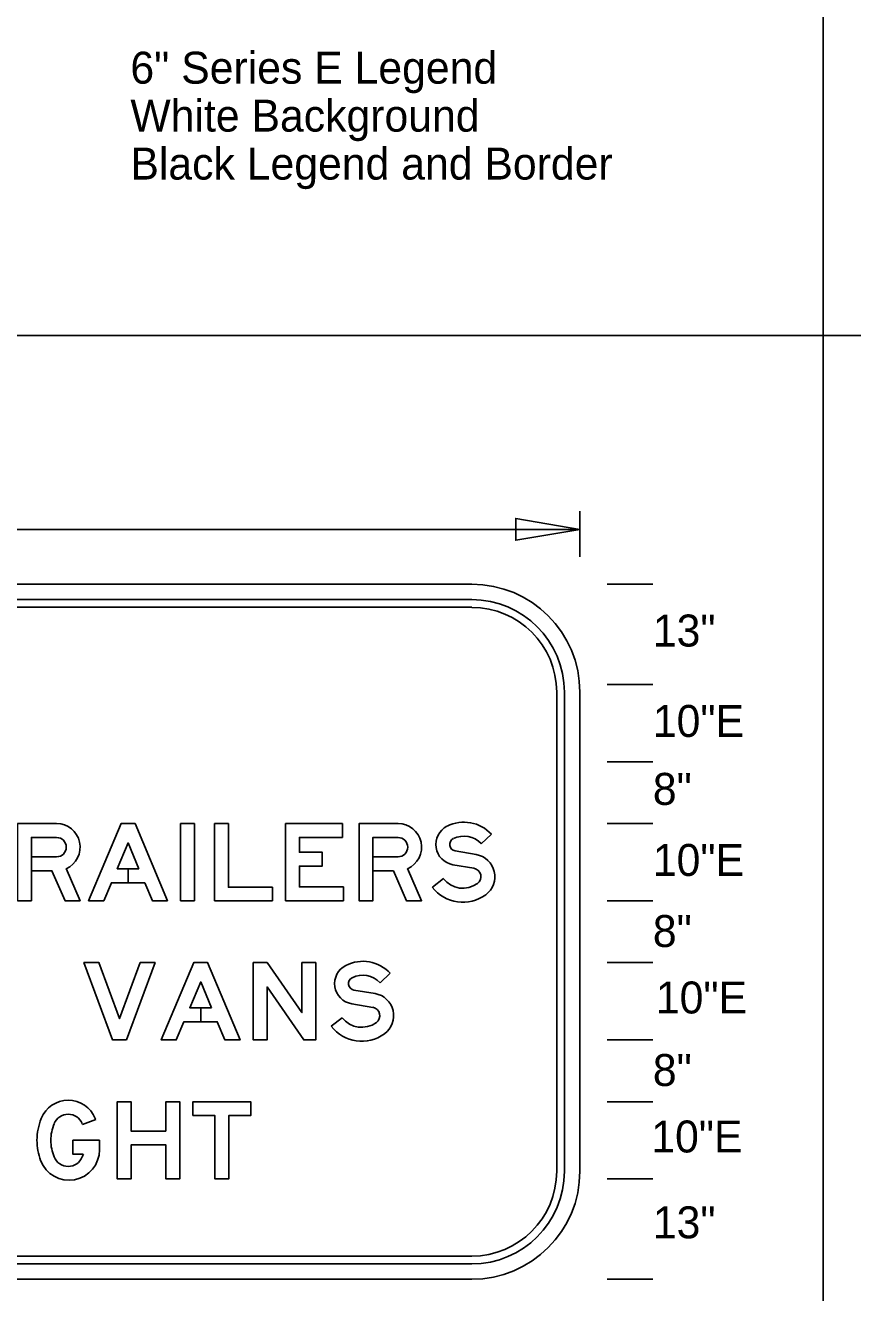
# Model space of a CAD drawing. Extents: x 0 to 770, y 0 to 495.
# Drawn here: x 297.9 to 388.5, y 225.2 to 363.9 of the extents above; entities that cross this region are included whole.
import ezdxf

# ---------------------------------------------------------------- set-up
doc = ezdxf.new("R2010")
doc.units = 0
for name, color, linetype in [('Dimension', 7, 'Continuous'), ('GSBWFill', 7, 'Continuous'), ('GSColorFill', 7, 'Continuous'), ('GSDims', 7, 'Continuous'), ('GSOutline', 7, 'Continuous'), ('SheetLines_dp', 7, 'Continuous'), ('TextStructures', 7, 'Continuous')]:
    doc.layers.add(name, color=color, linetype=linetype)

msp = doc.modelspace()

# ---------------------------------------------------------------- linework, layer by layer
at = {"layer": 'Dimension'}
msp.add_lwpolyline([(358.65, 308.76), (351.63, 309.95), (351.63, 307.57)], close=True, dxfattribs=at)
at = {"layer": 'GSBWFill'}
for p, q in [((346.81, 302.76), (223.31, 302.76)), ((346.81, 301.07), (223.31, 301.07)), ((223.31, 300.23), (346.81, 300.23)), ((356.11, 290.92), (356.11, 238.48)), ((356.96, 238.48), (356.96, 290.92)), ((358.65, 238.48), (358.65, 290.92)), ((347.85, 274.34), (348.96, 275.38)), ((347.3, 273.15), (344.99, 273.54)), ((344.74, 272.04), (347.05, 271.65)), ((343.7, 270.52), (342.49, 269.59)), ((336.77, 259.12), (337.88, 260.16)), ((336.22, 257.93), (333.91, 258.31)), ((333.66, 256.81), (335.96, 256.42)), ((332.62, 255.29), (331.41, 254.36)), ((304.18, 243.61), (305.62, 244.13)), ((306.04, 240.82), (306.04, 241.86)), ((346.81, 229.18), (223.32, 229.18)), ((223.32, 228.33), (346.81, 228.33)), ((223.31, 226.64), (346.81, 226.64))]:
    msp.add_line(p, q, dxfattribs=at)
for points in [[(301.34, 276.54), (297.07, 276.54), (297.07, 268.09), (298.59, 268.09), (298.59, 275.02), (301.34, 275.02)], [(338.73, 276.54), (334.46, 276.54), (334.46, 268.09), (335.98, 268.09), (335.98, 275.02), (338.73, 275.02)], [(301.34, 272.91), (298.59, 272.91), (298.59, 271.38)], [(338.73, 272.91), (335.98, 272.91), (335.98, 271.38)], [(298.59, 271.38), (300.83, 271.38), (302.26, 268.09), (303.92, 268.09), (302.4, 271.61)], [(335.98, 271.38), (338.22, 271.38), (339.65, 268.09), (341.31, 268.09), (339.78, 271.61)], [(306.04, 241.86), (303.12, 241.86), (303.12, 240.34), (304.26, 240.34)]]:
    msp.add_lwpolyline(points, dxfattribs=at)
for points in [[(310.35, 271.6), (309.17, 271.6), (309.17, 270.07), (310.99, 270.07), (311.83, 268.09), (313.48, 268.09), (309.93, 276.54), (308.4, 276.54), (304.85, 268.09), (306.5, 268.09), (307.34, 270.07), (309.17, 270.07), (309.17, 271.6), (307.98, 271.6), (309.17, 274.42)], [(314.92, 268.09), (314.92, 276.54), (316.44, 276.54), (316.44, 268.09)], [(324.98, 268.09), (324.98, 269.57), (320.16, 269.57), (320.16, 276.54), (318.64, 276.54), (318.64, 268.09)], [(332.76, 269.61), (327.94, 269.61), (327.94, 271.88), (330.44, 271.88), (330.44, 273.41), (327.94, 273.41), (327.94, 275.02), (332.64, 275.02), (332.64, 276.54), (326.42, 276.54), (326.42, 268.09), (332.76, 268.09)], [(309, 252.86), (307.47, 252.86), (304.34, 261.32), (305.97, 261.32), (308.24, 255.19), (310.5, 261.32), (312.13, 261.32)], [(318.31, 256.37), (317.12, 256.37), (317.12, 254.85), (318.94, 254.85), (319.78, 252.86), (321.43, 252.86), (317.88, 261.32), (316.36, 261.32), (312.8, 252.86), (314.45, 252.86), (315.29, 254.85), (317.12, 254.85), (317.12, 256.37), (315.93, 256.37), (317.12, 259.2)], [(329.72, 261.32), (329.72, 252.86), (328.41, 252.86), (324.39, 258.65), (324.39, 252.86), (322.87, 252.86), (322.87, 261.32), (324.4, 261.32), (328.2, 255.84), (328.2, 261.32)], [(313.31, 242.88), (309.5, 242.88), (309.5, 246.09), (307.98, 246.09), (307.98, 237.64), (309.5, 237.64), (309.5, 241.36), (313.31, 241.36), (313.31, 237.64), (314.83, 237.64), (314.83, 246.09), (313.31, 246.09)], [(316.27, 244.57), (318.68, 244.57), (318.68, 237.64), (320.2, 237.64), (320.2, 244.57), (322.61, 244.57), (322.61, 246.09), (316.27, 246.09)]]:
    msp.add_lwpolyline(points, close=True, dxfattribs=at)
for centre, radius, start, end in [((346.81, 290.92), 11.84, 0, 90), ((346.81, 290.92), 10.15, 0, 90), ((346.81, 290.92), 9.3, 0, 90), ((345.11, 274.25), 2.24, 116.9123, 260.4087), ((345.96, 272.59), 4.1, 42.8759, 116.9123), ((345.11, 274.25), 0.719, 116.9123, 260.4087), ((345.96, 272.59), 2.58, 42.8759, 116.9123), ((346.89, 270.73), 2.45, 306.123, 80.4087), ((346.89, 270.73), 0.93, 306.123, 80.4087), ((345.84, 272.17), 4.23, 217.5895, 306.123), ((345.84, 272.17), 2.71, 217.5895, 306.123), ((302.61, 243.05), 3.19, 22.4256, 157.5744), ((305.49, 241.86), 6.3, 157.5744, 180), ((302.61, 243.05), 1.67, 22.4256, 157.5744), ((299.74, 241.86), 6.3, 21.0425, 22.4256), ((305.49, 241.86), 4.78, 157.5744, 180), ((299.74, 241.86), 4.78, 21.4721, 22.4256), ((305.49, 241.86), 6.3, 180, 200.6303), ((305.49, 241.86), 4.78, 180, 202.4256), ((302.71, 240.82), 3.33, 200.6303, 0), ((299.74, 241.86), 4.78, 337.5744, 341.4227), ((302.61, 240.68), 1.67, 202.4256, 337.5744), ((346.81, 238.48), 10.15, 270, 0), ((346.81, 238.48), 9.3, 270, 0), ((346.81, 238.48), 11.84, 270, 0)]:
    msp.add_arc(centre, radius, start, end, dxfattribs=at)
for centre, major_axis, start_param, end_param in [((301.34, 273.96), (0, 2.58), 3.562504, 6.283185), ((338.73, 273.96), (0, 2.58), 3.562504, 6.283185), ((301.34, 273.96), (0, 1.06), 3.141593, 6.283185), ((338.73, 273.96), (0, 1.06), 3.141593, 6.283185), ((334.03, 259.02), (0, 2.24), 0.469708, 2.974193), ((334.88, 257.36), (0, 4.1), 5.460714, 6.752893), ((334.03, 259.02), (0, 0.719), 0.469708, 2.974193), ((334.88, 257.36), (0, 2.58), 5.460714, 6.752893), ((335.81, 255.51), (0, 2.45), 3.772058, 6.115786), ((335.81, 255.51), (0, 0.93), 3.772058, 6.115786), ((334.76, 256.94), (0, 4.23), 2.226857, 3.772058), ((334.76, 256.94), (0, 2.71), 2.226857, 3.772058)]:
    msp.add_ellipse(centre, major_axis=major_axis, ratio=0.999994, start_param=start_param, end_param=end_param, dxfattribs=at)
at = {"layer": 'GSColorFill'}
for p, q in [((347.85, 274.34), (348.96, 275.38)), ((347.3, 273.15), (344.99, 273.54)), ((344.74, 272.04), (347.05, 271.65)), ((343.7, 270.52), (342.49, 269.59)), ((336.77, 259.12), (337.88, 260.16)), ((336.22, 257.93), (333.91, 258.31)), ((333.66, 256.81), (335.96, 256.42)), ((332.62, 255.29), (331.41, 254.36)), ((304.18, 243.61), (305.62, 244.13)), ((306.04, 240.82), (306.04, 241.86))]:
    msp.add_line(p, q, dxfattribs=at)
for points in [[(301.34, 276.54), (297.07, 276.54), (297.07, 268.09), (298.59, 268.09), (298.59, 275.02), (301.34, 275.02)], [(338.73, 276.54), (334.46, 276.54), (334.46, 268.09), (335.98, 268.09), (335.98, 275.02), (338.73, 275.02)], [(301.34, 272.91), (298.59, 272.91), (298.59, 271.38)], [(338.73, 272.91), (335.98, 272.91), (335.98, 271.38)], [(298.59, 271.38), (300.83, 271.38), (302.26, 268.09), (303.92, 268.09), (302.4, 271.61)], [(335.98, 271.38), (338.22, 271.38), (339.65, 268.09), (341.31, 268.09), (339.78, 271.61)], [(306.04, 241.86), (303.12, 241.86), (303.12, 240.34), (304.26, 240.34)]]:
    msp.add_lwpolyline(points, dxfattribs=at)
for points in [[(310.35, 271.6), (309.17, 271.6), (309.17, 270.07), (310.99, 270.07), (311.83, 268.09), (313.48, 268.09), (309.93, 276.54), (308.4, 276.54), (304.85, 268.09), (306.5, 268.09), (307.34, 270.07), (309.17, 270.07), (309.17, 271.6), (307.98, 271.6), (309.17, 274.42)], [(314.92, 268.09), (314.92, 276.54), (316.44, 276.54), (316.44, 268.09)], [(324.98, 268.09), (324.98, 269.57), (320.16, 269.57), (320.16, 276.54), (318.64, 276.54), (318.64, 268.09)], [(332.76, 269.61), (327.94, 269.61), (327.94, 271.88), (330.44, 271.88), (330.44, 273.41), (327.94, 273.41), (327.94, 275.02), (332.64, 275.02), (332.64, 276.54), (326.42, 276.54), (326.42, 268.09), (332.76, 268.09)], [(309, 252.86), (307.47, 252.86), (304.34, 261.32), (305.97, 261.32), (308.24, 255.19), (310.5, 261.32), (312.13, 261.32)], [(318.31, 256.37), (317.12, 256.37), (317.12, 254.85), (318.94, 254.85), (319.78, 252.86), (321.43, 252.86), (317.88, 261.32), (316.36, 261.32), (312.8, 252.86), (314.45, 252.86), (315.29, 254.85), (317.12, 254.85), (317.12, 256.37), (315.93, 256.37), (317.12, 259.2)], [(329.72, 261.32), (329.72, 252.86), (328.41, 252.86), (324.39, 258.65), (324.39, 252.86), (322.87, 252.86), (322.87, 261.32), (324.4, 261.32), (328.2, 255.84), (328.2, 261.32)], [(313.31, 242.88), (309.5, 242.88), (309.5, 246.09), (307.98, 246.09), (307.98, 237.64), (309.5, 237.64), (309.5, 241.36), (313.31, 241.36), (313.31, 237.64), (314.83, 237.64), (314.83, 246.09), (313.31, 246.09)], [(316.27, 244.57), (318.68, 244.57), (318.68, 237.64), (320.2, 237.64), (320.2, 244.57), (322.61, 244.57), (322.61, 246.09), (316.27, 246.09)]]:
    msp.add_lwpolyline(points, close=True, dxfattribs=at)
for centre, radius, start, end in [((345.11, 274.25), 2.24, 116.9123, 260.4087), ((345.96, 272.59), 4.1, 42.8759, 116.9123), ((345.11, 274.25), 0.719, 116.9123, 260.4087), ((345.96, 272.59), 2.58, 42.8759, 116.9123), ((346.89, 270.73), 2.45, 306.123, 80.4087), ((346.89, 270.73), 0.93, 306.123, 80.4087), ((345.84, 272.17), 4.23, 217.5895, 306.123), ((345.84, 272.17), 2.71, 217.5895, 306.123), ((302.61, 243.05), 3.19, 22.4256, 157.5744), ((305.49, 241.86), 6.3, 157.5744, 180), ((302.61, 243.05), 1.67, 22.4256, 157.5744), ((299.74, 241.86), 6.3, 21.0425, 22.4256), ((305.49, 241.86), 4.78, 157.5744, 180), ((299.74, 241.86), 4.78, 21.4721, 22.4256), ((305.49, 241.86), 6.3, 180, 200.6303), ((305.49, 241.86), 4.78, 180, 202.4256), ((302.71, 240.82), 3.33, 200.6303, 0), ((299.74, 241.86), 4.78, 337.5744, 341.4227), ((302.61, 240.68), 1.67, 202.4256, 337.5744)]:
    msp.add_arc(centre, radius, start, end, dxfattribs=at)
for centre, major_axis, start_param, end_param in [((301.34, 273.96), (0, 2.58), 3.562504, 6.283185), ((338.73, 273.96), (0, 2.58), 3.562504, 6.283185), ((301.34, 273.96), (0, 1.06), 3.141593, 6.283185), ((338.73, 273.96), (0, 1.06), 3.141593, 6.283185), ((334.03, 259.02), (0, 2.24), 0.469708, 2.974193), ((334.88, 257.36), (0, 4.1), 5.460714, 6.752893), ((334.03, 259.02), (0, 0.719), 0.469708, 2.974193), ((334.88, 257.36), (0, 2.58), 5.460714, 6.752893), ((335.81, 255.51), (0, 2.45), 3.772058, 6.115786), ((335.81, 255.51), (0, 0.93), 3.772058, 6.115786), ((334.76, 256.94), (0, 4.23), 2.226857, 3.772058), ((334.76, 256.94), (0, 2.71), 2.226857, 3.772058)]:
    msp.add_ellipse(centre, major_axis=major_axis, ratio=0.999994, start_param=start_param, end_param=end_param, dxfattribs=at)
at = {"layer": 'GSDims'}
for p, q in [((358.65, 305.76), (358.65, 310.76)), ((211.47, 308.76), (358.65, 308.76)), ((361.64, 302.76), (366.64, 302.76)), ((361.64, 291.77), (366.64, 291.77)), ((361.64, 291.77), (366.64, 291.77)), ((361.64, 283.31), (366.64, 283.31)), ((361.64, 283.31), (366.64, 283.31)), ((361.64, 276.54), (366.64, 276.54)), ((361.64, 276.54), (366.64, 276.54)), ((361.64, 268.09), (366.64, 268.09)), ((361.64, 268.09), (366.64, 268.09)), ((361.64, 261.32), (366.64, 261.32)), ((361.64, 261.32), (366.64, 261.32)), ((361.64, 252.86), (366.64, 252.86)), ((361.64, 252.86), (366.64, 252.86)), ((361.64, 246.09), (366.64, 246.09)), ((361.64, 246.09), (366.64, 246.09)), ((361.64, 237.64), (366.64, 237.64)), ((361.64, 237.64), (366.64, 237.64)), ((361.64, 226.64), (366.64, 226.64))]:
    msp.add_line(p, q, dxfattribs=at)
at = {"layer": 'GSOutline'}
for p, q in [((347.85, 274.34), (348.96, 275.38)), ((347.3, 273.15), (344.99, 273.54)), ((298.59, 272.91), (301.34, 272.91)), ((335.98, 272.91), (338.73, 272.91)), ((344.74, 272.04), (347.05, 271.65)), ((343.7, 270.52), (342.49, 269.59)), ((336.77, 259.12), (337.88, 260.16)), ((336.22, 257.93), (333.91, 258.31)), ((333.66, 256.81), (335.96, 256.42)), ((332.62, 255.29), (331.41, 254.36)), ((304.18, 243.61), (305.62, 244.13)), ((306.04, 240.82), (306.04, 241.86))]:
    msp.add_line(p, q, dxfattribs=at)
for points in [[(301.34, 276.54), (297.07, 276.54), (297.07, 268.09), (298.59, 268.09), (298.59, 271.38), (300.83, 271.38)], [(338.73, 276.54), (334.46, 276.54), (334.46, 268.09), (335.98, 268.09), (335.98, 271.38), (338.22, 271.38)], [(301.34, 275.02), (298.59, 275.02), (298.59, 272.91)], [(338.73, 275.02), (335.98, 275.02), (335.98, 272.91)], [(300.83, 271.38), (302.26, 268.09), (303.92, 268.09), (302.4, 271.61)], [(338.22, 271.38), (339.65, 268.09), (341.31, 268.09), (339.78, 271.61)], [(306.04, 241.86), (303.12, 241.86), (303.12, 240.34), (304.26, 240.34)]]:
    msp.add_lwpolyline(points, dxfattribs=at)
for points in [[(307.34, 270.07), (310.99, 270.07), (311.83, 268.09), (313.48, 268.09), (309.93, 276.54), (308.4, 276.54), (304.85, 268.09), (306.5, 268.09)], [(314.92, 268.09), (314.92, 276.54), (316.44, 276.54), (316.44, 268.09)], [(324.98, 268.09), (324.98, 269.57), (320.16, 269.57), (320.16, 276.54), (318.64, 276.54), (318.64, 268.09)], [(332.76, 269.61), (327.94, 269.61), (327.94, 271.88), (330.44, 271.88), (330.44, 273.41), (327.94, 273.41), (327.94, 275.02), (332.64, 275.02), (332.64, 276.54), (326.42, 276.54), (326.42, 268.09), (332.76, 268.09)], [(310.35, 271.6), (309.17, 274.42), (307.98, 271.6)], [(309, 252.86), (307.47, 252.86), (304.34, 261.32), (305.97, 261.32), (308.24, 255.19), (310.5, 261.32), (312.13, 261.32)], [(315.29, 254.85), (318.94, 254.85), (319.78, 252.86), (321.43, 252.86), (317.88, 261.32), (316.36, 261.32), (312.8, 252.86), (314.45, 252.86)], [(329.72, 261.32), (329.72, 252.86), (328.41, 252.86), (324.39, 258.65), (324.39, 252.86), (322.87, 252.86), (322.87, 261.32), (324.4, 261.32), (328.2, 255.84), (328.2, 261.32)], [(318.31, 256.37), (317.12, 259.2), (315.93, 256.37)], [(313.31, 242.88), (309.5, 242.88), (309.5, 246.09), (307.98, 246.09), (307.98, 237.64), (309.5, 237.64), (309.5, 241.36), (313.31, 241.36), (313.31, 237.64), (314.83, 237.64), (314.83, 246.09), (313.31, 246.09)], [(316.27, 244.57), (318.68, 244.57), (318.68, 237.64), (320.2, 237.64), (320.2, 244.57), (322.61, 244.57), (322.61, 246.09), (316.27, 246.09)]]:
    msp.add_lwpolyline(points, close=True, dxfattribs=at)
for centre, radius, start, end in [((345.11, 274.25), 2.24, 116.9123, 260.4087), ((345.96, 272.59), 4.1, 42.8759, 116.9123), ((345.11, 274.25), 0.719, 116.9123, 260.4087), ((345.96, 272.59), 2.58, 42.8759, 116.9123), ((346.89, 270.73), 2.45, 306.123, 80.4087), ((346.89, 270.73), 0.93, 306.123, 80.4087), ((345.84, 272.17), 4.23, 217.5895, 306.123), ((345.84, 272.17), 2.71, 217.5895, 306.123), ((302.61, 243.05), 3.19, 22.4256, 157.5744), ((305.49, 241.86), 6.3, 157.5744, 180), ((302.61, 243.05), 1.67, 22.4256, 157.5744), ((299.74, 241.86), 6.3, 21.0425, 22.4256), ((305.49, 241.86), 4.78, 157.5744, 180), ((299.74, 241.86), 4.78, 21.4721, 22.4256), ((305.49, 241.86), 6.3, 180, 200.6303), ((305.49, 241.86), 4.78, 180, 202.4256), ((302.71, 240.82), 3.33, 200.6303, 0), ((299.74, 241.86), 4.78, 337.5744, 341.4227), ((302.61, 240.68), 1.67, 202.4256, 337.5744)]:
    msp.add_arc(centre, radius, start, end, dxfattribs=at)
for centre, major_axis, start_param, end_param in [((301.34, 273.96), (0, 2.58), 3.562504, 6.283185), ((338.73, 273.96), (0, 2.58), 3.562504, 6.283185), ((301.34, 273.96), (0, 1.06), 3.141593, 6.283185), ((338.73, 273.96), (0, 1.06), 3.141593, 6.283185), ((334.03, 259.02), (0, 2.24), 0.469708, 2.974193), ((334.88, 257.36), (0, 4.1), 5.460714, 6.752893), ((334.03, 259.02), (0, 0.719), 0.469708, 2.974193), ((334.88, 257.36), (0, 2.58), 5.460714, 6.752893), ((335.81, 255.51), (0, 2.45), 3.772058, 6.115786), ((335.81, 255.51), (0, 0.93), 3.772058, 6.115786), ((334.76, 256.94), (0, 4.23), 2.226857, 3.772058), ((334.76, 256.94), (0, 2.71), 2.226857, 3.772058)]:
    msp.add_ellipse(centre, major_axis=major_axis, ratio=0.999994, start_param=start_param, end_param=end_param, dxfattribs=at)
at = {"layer": 'SheetLines_dp'}
for p, q in [((385.3, 0), (385.3, 495)), ((770, 330), (0, 330))]:
    msp.add_line(p, q, dxfattribs=at)

# ---------------------------------------------------------------- texts
at = {"layer": 'TextStructures'}
for s, p in [('6" Series E Legend', (309.42, 357.56)), ('White Background', (309.42, 352.31)), ('Black Legend and Border', (309.42, 347.06)), ('13"', (366.64, 295.93)), ('10"E', (366.64, 286.03)), ('8"', (366.64, 278.59)), ('10"E', (366.64, 270.81)), ('8"', (366.64, 263.03)), ('10"E', (366.97, 255.75)), ('8"', (366.64, 247.81)), ('10"E', (366.47, 240.53)), ('13"', (366.64, 231.13))]:
    msp.add_text(s, height=3.5, dxfattribs=at).set_placement(p)

doc.saveas('drawing.dxf')
